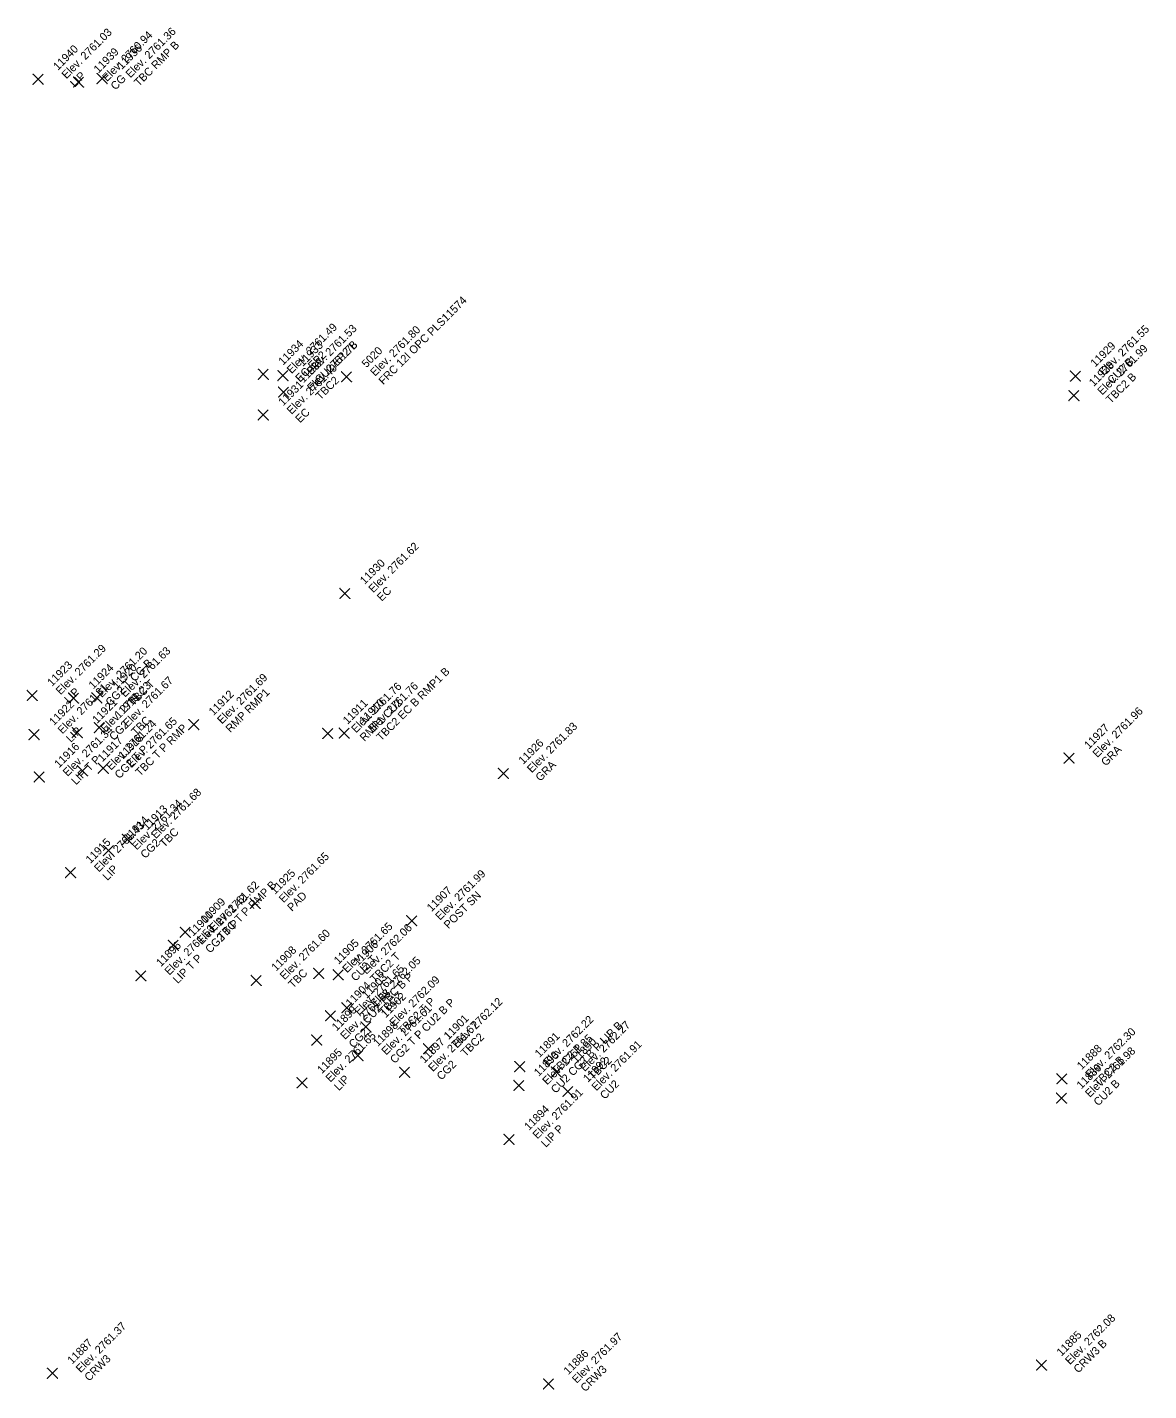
# Model space of a CAD drawing. Extents: x 2493999 to 2503109, y 700767 to 706646.
# Drawn here: x 2502309.37 to 2502343.02, y 701969.92 to 702010.81 of the extents above; entities that cross this region are included whole.
import ezdxf

# ---------------------------------------------------------------- set-up
doc = ezdxf.new("R2010")
doc.units = 0
doc.layers.add('ALG_CL_BLUE_Horiz', color=7, linetype='Continuous')
doc.layers.add('DES_SURFACE_Existing-Ground', color=7, linetype='Continuous')

msp = doc.modelspace()

# ---------------------------------------------------------------- linework, layer by layer
at = {"layer": 'ALG_CL_BLUE_Horiz'}
for points in [[(2502309.698, 702009.247), (2502309.548, 702009.397), (2502309.698, 702009.247), (2502309.548, 702009.097), (2502309.698, 702009.247), (2502309.848, 702009.097), (2502309.698, 702009.247), (2502309.848, 702009.397)], [(2502310.914, 702009.163), (2502310.764, 702009.313), (2502310.914, 702009.163), (2502310.764, 702009.013), (2502310.914, 702009.163), (2502311.064, 702009.013), (2502310.914, 702009.163), (2502311.064, 702009.313)], [(2502311.617, 702009.271), (2502311.467, 702009.421), (2502311.617, 702009.271), (2502311.467, 702009.121), (2502311.617, 702009.271), (2502311.767, 702009.121), (2502311.617, 702009.271), (2502311.767, 702009.421)], [(2502316.456, 702000.403), (2502316.306, 702000.553), (2502316.456, 702000.403), (2502316.306, 702000.253), (2502316.456, 702000.403), (2502316.606, 702000.253), (2502316.456, 702000.403), (2502316.606, 702000.553)], [(2502317.043, 702000.364), (2502316.893, 702000.514), (2502317.043, 702000.364), (2502316.893, 702000.214), (2502317.043, 702000.364), (2502317.193, 702000.214), (2502317.043, 702000.364), (2502317.193, 702000.514)], [(2502318.954, 702000.326), (2502318.804, 702000.476), (2502318.954, 702000.326), (2502318.804, 702000.176), (2502318.954, 702000.326), (2502319.104, 702000.176), (2502318.954, 702000.326), (2502319.104, 702000.476)], [(2502340.821, 702000.346), (2502340.671, 702000.496), (2502340.821, 702000.346), (2502340.671, 702000.196), (2502340.821, 702000.346), (2502340.971, 702000.196), (2502340.821, 702000.346), (2502340.971, 702000.496)], [(2502317.065, 701999.869), (2502316.915, 702000.019), (2502317.065, 701999.869), (2502316.915, 701999.719), (2502317.065, 701999.869), (2502317.215, 701999.719), (2502317.065, 701999.869), (2502317.215, 702000.019)], [(2502340.775, 701999.764), (2502340.625, 701999.914), (2502340.775, 701999.764), (2502340.625, 701999.614), (2502340.775, 701999.764), (2502340.925, 701999.614), (2502340.775, 701999.764), (2502340.925, 701999.914)], [(2502316.455, 701999.181), (2502316.305, 701999.331), (2502316.455, 701999.181), (2502316.305, 701999.031), (2502316.455, 701999.181), (2502316.605, 701999.031), (2502316.455, 701999.181), (2502316.605, 701999.331)], [(2502318.904, 701993.83), (2502318.754, 701993.98), (2502318.904, 701993.83), (2502318.754, 701993.68), (2502318.904, 701993.83), (2502319.054, 701993.68), (2502318.904, 701993.83), (2502319.054, 701993.98)], [(2502309.523, 701990.772), (2502309.373, 701990.922), (2502309.523, 701990.772), (2502309.373, 701990.622), (2502309.523, 701990.772), (2502309.673, 701990.622), (2502309.523, 701990.772), (2502309.673, 701990.922)], [(2502310.762, 701990.69), (2502310.612, 701990.84), (2502310.762, 701990.69), (2502310.612, 701990.54), (2502310.762, 701990.69), (2502310.912, 701990.54), (2502310.762, 701990.69), (2502310.912, 701990.84)], [(2502311.458, 701990.698), (2502311.308, 701990.848), (2502311.458, 701990.698), (2502311.308, 701990.548), (2502311.458, 701990.698), (2502311.608, 701990.548), (2502311.458, 701990.698), (2502311.608, 701990.848)], [(2502314.366, 701989.896), (2502314.216, 701990.046), (2502314.366, 701989.896), (2502314.216, 701989.746), (2502314.366, 701989.896), (2502314.516, 701989.746), (2502314.366, 701989.896), (2502314.516, 701990.046)], [(2502309.579, 701989.597), (2502309.429, 701989.747), (2502309.579, 701989.597), (2502309.429, 701989.447), (2502309.579, 701989.597), (2502309.729, 701989.447), (2502309.579, 701989.597), (2502309.729, 701989.747)], [(2502310.872, 701989.655), (2502310.722, 701989.805), (2502310.872, 701989.655), (2502310.722, 701989.505), (2502310.872, 701989.655), (2502311.022, 701989.505), (2502310.872, 701989.655), (2502311.022, 701989.805)], [(2502311.535, 701989.804), (2502311.385, 701989.954), (2502311.535, 701989.804), (2502311.385, 701989.654), (2502311.535, 701989.804), (2502311.685, 701989.654), (2502311.535, 701989.804), (2502311.685, 701989.954)], [(2502318.389, 701989.63), (2502318.239, 701989.78), (2502318.389, 701989.63), (2502318.239, 701989.48), (2502318.389, 701989.63), (2502318.539, 701989.48), (2502318.389, 701989.63), (2502318.539, 701989.78)], [(2502318.885, 701989.641), (2502318.735, 701989.791), (2502318.885, 701989.641), (2502318.735, 701989.491), (2502318.885, 701989.641), (2502319.035, 701989.491), (2502318.885, 701989.641), (2502319.035, 701989.791)], [(2502340.63, 701988.891), (2502340.48, 701989.041), (2502340.63, 701988.891), (2502340.48, 701988.741), (2502340.63, 701988.891), (2502340.78, 701988.741), (2502340.63, 701988.891), (2502340.78, 701989.041)], [(2502309.734, 701988.326), (2502309.584, 701988.476), (2502309.734, 701988.326), (2502309.584, 701988.176), (2502309.734, 701988.326), (2502309.884, 701988.176), (2502309.734, 701988.326), (2502309.884, 701988.476)], [(2502311.034, 701988.51), (2502310.884, 701988.66), (2502311.034, 701988.51), (2502310.884, 701988.36), (2502311.034, 701988.51), (2502311.184, 701988.36), (2502311.034, 701988.51), (2502311.184, 701988.66)], [(2502311.654, 701988.588), (2502311.504, 701988.738), (2502311.654, 701988.588), (2502311.504, 701988.438), (2502311.654, 701988.588), (2502311.804, 701988.438), (2502311.654, 701988.588), (2502311.804, 701988.738)], [(2502323.661, 701988.433), (2502323.511, 701988.583), (2502323.661, 701988.433), (2502323.511, 701988.283), (2502323.661, 701988.433), (2502323.811, 701988.283), (2502323.661, 701988.433), (2502323.811, 701988.583)], [(2502312.38, 701986.455), (2502312.23, 701986.605), (2502312.38, 701986.455), (2502312.23, 701986.305), (2502312.38, 701986.455), (2502312.53, 701986.305), (2502312.38, 701986.455), (2502312.53, 701986.605)], [(2502311.809, 701986.118), (2502311.659, 701986.268), (2502311.809, 701986.118), (2502311.659, 701985.968), (2502311.809, 701986.118), (2502311.959, 701985.968), (2502311.809, 701986.118), (2502311.959, 701986.268)], [(2502310.672, 701985.458), (2502310.522, 701985.608), (2502310.672, 701985.458), (2502310.522, 701985.308), (2502310.672, 701985.458), (2502310.822, 701985.308), (2502310.672, 701985.458), (2502310.822, 701985.608)], [(2502316.214, 701984.533), (2502316.064, 701984.683), (2502316.214, 701984.533), (2502316.064, 701984.383), (2502316.214, 701984.533), (2502316.364, 701984.383), (2502316.214, 701984.533), (2502316.364, 701984.683)], [(2502320.909, 701984.013), (2502320.759, 701984.163), (2502320.909, 701984.013), (2502320.759, 701983.863), (2502320.909, 701984.013), (2502321.059, 701983.863), (2502320.909, 701984.013), (2502321.059, 701984.163)], [(2502314.114, 701983.671), (2502313.964, 701983.821), (2502314.114, 701983.671), (2502313.964, 701983.521), (2502314.114, 701983.671), (2502314.264, 701983.521), (2502314.114, 701983.671), (2502314.264, 701983.821)], [(2502313.753, 701983.28), (2502313.603, 701983.43), (2502313.753, 701983.28), (2502313.603, 701983.13), (2502313.753, 701983.28), (2502313.903, 701983.13), (2502313.753, 701983.28), (2502313.903, 701983.43)], [(2502312.785, 701982.365), (2502312.635, 701982.515), (2502312.785, 701982.365), (2502312.635, 701982.215), (2502312.785, 701982.365), (2502312.935, 701982.215), (2502312.785, 701982.365), (2502312.935, 701982.515)], [(2502316.245, 701982.226), (2502316.095, 701982.376), (2502316.245, 701982.226), (2502316.095, 701982.076), (2502316.245, 701982.226), (2502316.395, 701982.076), (2502316.245, 701982.226), (2502316.395, 701982.376)], [(2502318.12, 701982.435), (2502317.97, 701982.585), (2502318.12, 701982.435), (2502317.97, 701982.285), (2502318.12, 701982.435), (2502318.27, 701982.285), (2502318.12, 701982.435), (2502318.27, 701982.585)], [(2502318.702, 701982.392), (2502318.552, 701982.542), (2502318.702, 701982.392), (2502318.552, 701982.242), (2502318.702, 701982.392), (2502318.852, 701982.242), (2502318.702, 701982.392), (2502318.852, 701982.542)], [(2502318.963, 701981.407), (2502318.813, 701981.557), (2502318.963, 701981.407), (2502318.813, 701981.257), (2502318.963, 701981.407), (2502319.113, 701981.257), (2502318.963, 701981.407), (2502319.113, 701981.557)], [(2502318.474, 701981.164), (2502318.324, 701981.314), (2502318.474, 701981.164), (2502318.324, 701981.014), (2502318.474, 701981.164), (2502318.624, 701981.014), (2502318.474, 701981.164), (2502318.624, 701981.314)], [(2502319.533, 701980.831), (2502319.383, 701980.981), (2502319.533, 701980.831), (2502319.383, 701980.681), (2502319.533, 701980.831), (2502319.683, 701980.681), (2502319.533, 701980.831), (2502319.683, 701980.981)], [(2502318.058, 701980.434), (2502317.908, 701980.584), (2502318.058, 701980.434), (2502317.908, 701980.284), (2502318.058, 701980.434), (2502318.208, 701980.284), (2502318.058, 701980.434), (2502318.208, 701980.584)], [(2502321.416, 701980.175), (2502321.266, 701980.325), (2502321.416, 701980.175), (2502321.266, 701980.025), (2502321.416, 701980.175), (2502321.566, 701980.025), (2502321.416, 701980.175), (2502321.566, 701980.325)], [(2502319.296, 701979.969), (2502319.146, 701980.119), (2502319.296, 701979.969), (2502319.146, 701979.819), (2502319.296, 701979.969), (2502319.446, 701979.819), (2502319.296, 701979.969), (2502319.446, 701980.119)], [(2502324.147, 701979.64), (2502323.997, 701979.79), (2502324.147, 701979.64), (2502323.997, 701979.49), (2502324.147, 701979.64), (2502324.297, 701979.49), (2502324.147, 701979.64), (2502324.297, 701979.79)], [(2502320.696, 701979.472), (2502320.546, 701979.622), (2502320.696, 701979.472), (2502320.546, 701979.322), (2502320.696, 701979.472), (2502320.846, 701979.322), (2502320.696, 701979.472), (2502320.846, 701979.622)], [(2502325.25, 701979.474), (2502325.1, 701979.624), (2502325.25, 701979.474), (2502325.1, 701979.324), (2502325.25, 701979.474), (2502325.4, 701979.324), (2502325.25, 701979.474), (2502325.4, 701979.624)], [(2502340.414, 701979.275), (2502340.264, 701979.425), (2502340.414, 701979.275), (2502340.264, 701979.125), (2502340.414, 701979.275), (2502340.564, 701979.125), (2502340.414, 701979.275), (2502340.564, 701979.425)], [(2502317.617, 701979.156), (2502317.467, 701979.306), (2502317.617, 701979.156), (2502317.467, 701979.006), (2502317.617, 701979.156), (2502317.767, 701979.006), (2502317.617, 701979.156), (2502317.767, 701979.306)], [(2502324.123, 701979.075), (2502323.973, 701979.225), (2502324.123, 701979.075), (2502323.973, 701978.925), (2502324.123, 701979.075), (2502324.273, 701978.925), (2502324.123, 701979.075), (2502324.273, 701979.225)], [(2502325.596, 701978.896), (2502325.446, 701979.046), (2502325.596, 701978.896), (2502325.446, 701978.746), (2502325.596, 701978.896), (2502325.746, 701978.746), (2502325.596, 701978.896), (2502325.746, 701979.046)], [(2502340.405, 701978.697), (2502340.255, 701978.847), (2502340.405, 701978.697), (2502340.255, 701978.547), (2502340.405, 701978.697), (2502340.555, 701978.547), (2502340.405, 701978.697), (2502340.555, 701978.847)], [(2502323.831, 701977.454), (2502323.681, 701977.604), (2502323.831, 701977.454), (2502323.681, 701977.304), (2502323.831, 701977.454), (2502323.981, 701977.304), (2502323.831, 701977.454), (2502323.981, 701977.604)], [(2502339.805, 701970.687), (2502339.655, 701970.837), (2502339.805, 701970.687), (2502339.655, 701970.537), (2502339.805, 701970.687), (2502339.955, 701970.537), (2502339.805, 701970.687), (2502339.955, 701970.837)], [(2502310.127, 701970.443), (2502309.977, 701970.593), (2502310.127, 701970.443), (2502309.977, 701970.293), (2502310.127, 701970.443), (2502310.277, 701970.293), (2502310.127, 701970.443), (2502310.277, 701970.593)], [(2502325.012, 701970.126), (2502324.862, 701970.276), (2502325.012, 701970.126), (2502324.862, 701969.976), (2502325.012, 701970.126), (2502325.162, 701969.976), (2502325.012, 701970.126), (2502325.162, 701970.276)]]:
    msp.add_lwpolyline(points, dxfattribs=at)

# ---------------------------------------------------------------- texts
at = {"layer": 'DES_SURFACE_Existing-Ground'}
for s, p in [('Elev. 2761.03', (2502310.547, 702009.247)), ('Elev. 2760.94', (2502311.763, 702009.163)), ('Elev. 2761.36', (2502312.466, 702009.271)), ('11940', (2502310.292, 702009.502)), ('11939', (2502311.508, 702009.418)), ('11936', (2502312.211, 702009.526)), ('TBC RMP B', (2502312.72, 702009.016)), ('LIP', (2502310.801, 702008.992)), ('CG', (2502312.017, 702008.908)), ('FRC 12I OPC PLS11574', (2502320.057, 702000.071)), ('Elev. 2761.49', (2502317.305, 702000.403)), ('Elev. 2761.53', (2502317.892, 702000.364)), ('Elev. 2761.55', (2502341.67, 702000.346)), ('Elev. 2761.80', (2502319.803, 702000.326)), ('11934', (2502317.05, 702000.658)), ('EC EP2', (2502317.559, 702000.148)), ('11933', (2502317.637, 702000.619)), ('Elev. 2761.78', (2502317.914, 701999.869)), ('CU2 EP2 B', (2502318.146, 702000.109)), ('5020', (2502319.548, 702000.581)), ('11929', (2502341.415, 702000.601)), ('Elev. 2761.99', (2502341.624, 701999.764)), ('Elev. 2761.49', (2502317.304, 701999.181)), ('11932', (2502317.659, 702000.124)), ('11928', (2502341.369, 702000.019)), ('CU2 B', (2502341.924, 702000.091)), ('TBC2', (2502318.168, 701999.614)), ('TBC2 B', (2502341.878, 701999.509)), ('11931', (2502317.049, 701999.436)), ('EC', (2502317.558, 701998.926)), ('Elev. 2761.62', (2502319.753, 701993.83)), ('11930', (2502319.498, 701994.085)), ('EC', (2502320.007, 701993.575)), ('Elev. 2761.29', (2502310.372, 701990.772)), ('Elev. 2761.20', (2502311.611, 701990.69)), ('Elev. 2761.63', (2502312.307, 701990.698)), ('11923', (2502310.117, 701991.027)), ('11924', (2502311.356, 701990.945)), ('CG2 T CG B', (2502311.865, 701990.435)), ('11920', (2502312.052, 701990.953)), ('Elev. 2761.67', (2502312.384, 701989.804)), ('TBC T', (2502312.561, 701990.443)), ('Elev. 2761.69', (2502315.215, 701989.896)), ('TBC2 EC B RMP1 B', (2502319.988, 701989.386)), ('Elev. 2761.31', (2502310.428, 701989.597)), ('LIP', (2502310.626, 701990.517)), ('Elev. 2761.23', (2502311.721, 701989.655)), ('11919', (2502312.129, 701990.059)), ('11912', (2502314.96, 701990.151)), ('RMP RMP1', (2502315.469, 701989.641)), ('Elev. 2761.76', (2502319.238, 701989.63)), ('Elev. 2761.76', (2502319.734, 701989.641)), ('11922', (2502310.173, 701989.852)), ('11921', (2502311.466, 701989.91)), ('11911', (2502318.983, 701989.885)), ('RMP1 CU2', (2502319.492, 701989.375)), ('11910', (2502319.479, 701989.896)), ('Elev. 2761.96', (2502341.479, 701988.891)), ('Elev. 2761.24', (2502311.883, 701988.51)), ('CG2', (2502311.975, 701989.4)), ('Elev. 2761.65', (2502312.503, 701988.588)), ('TBC', (2502312.638, 701989.549)), ('Elev. 2761.34', (2502310.583, 701988.326)), ('LIP', (2502310.682, 701989.342)), ('11918', (2502312.248, 701988.843)), ('TBC T P RMP', (2502312.757, 701988.333)), ('Elev. 2761.83', (2502324.51, 701988.433)), ('11927', (2502341.224, 701989.146)), ('11916', (2502310.328, 701988.581)), ('11917', (2502311.628, 701988.765)), ('CG2 T P', (2502312.137, 701988.255)), ('11926', (2502324.255, 701988.688)), ('GRA', (2502341.733, 701988.636)), ('LIP T P', (2502310.837, 701988.071)), ('GRA', (2502324.764, 701988.178)), ('Elev. 2761.68', (2502313.229, 701986.455)), ('Elev. 2761.34', (2502312.658, 701986.118)), ('11914', (2502312.403, 701986.373)), ('11913', (2502312.974, 701986.71)), ('Elev. 2761.43', (2502311.521, 701985.458)), ('TBC', (2502313.483, 701986.2)), ('11915', (2502311.266, 701985.713)), ('CG2', (2502312.912, 701985.863)), ('Elev. 2761.65', (2502317.063, 701984.533)), ('LIP', (2502311.775, 701985.203)), ('11925', (2502316.808, 701984.788)), ('Elev. 2761.99', (2502321.758, 701984.013)), ('Elev. 2761.62', (2502314.963, 701983.671)), ('TBC T P RMP B', (2502315.217, 701983.416)), ('Elev. 2761.42', (2502314.602, 701983.28)), ('11909', (2502314.708, 701983.926)), ('PAD', (2502317.317, 701984.278)), ('11907', (2502321.503, 701984.268)), ('POST SN', (2502322.012, 701983.758)), ('11900', (2502314.347, 701983.535)), ('Elev. 2761.53', (2502313.634, 701982.365)), ('CG2 T P', (2502314.856, 701983.025)), ('Elev. 2761.65', (2502318.969, 701982.435)), ('Elev. 2762.06', (2502319.551, 701982.392)), ('Elev. 2761.60', (2502317.094, 701982.226)), ('11905', (2502318.714, 701982.69)), ('11896', (2502313.379, 701982.62)), ('11908', (2502316.839, 701982.481)), ('11906', (2502319.296, 701982.647)), ('TBC2 T', (2502319.805, 701982.137)), ('LIP T P', (2502313.888, 701982.11)), ('CU2 T', (2502319.223, 701982.18)), ('Elev. 2761.65', (2502319.323, 701981.164)), ('Elev. 2762.05', (2502319.812, 701981.407)), ('TBC', (2502317.348, 701981.971)), ('11903', (2502319.557, 701981.662)), ('CU2 TBC B P', (2502319.577, 701980.909)), ('Elev. 2762.09', (2502320.382, 701980.831)), ('Elev. 2761.58', (2502318.907, 701980.434)), ('11904', (2502319.068, 701981.419)), ('TBC2', (2502320.066, 701981.152)), ('11902', (2502320.127, 701981.086)), ('11899', (2502318.652, 701980.689)), ('Elev. 2761.61', (2502320.145, 701979.969)), ('CG2 T P CU2 B P', (2502320.399, 701979.714)), ('TBC2 T P', (2502320.636, 701980.576)), ('Elev. 2762.12', (2502322.265, 701980.175)), ('Elev. 2761.67', (2502321.545, 701979.472)), ('11901', (2502322.01, 701980.43)), ('Elev. 2762.22', (2502324.996, 701979.64)), ('Elev. 2762.27', (2502326.099, 701979.474)), ('Elev. 2761.65', (2502318.466, 701979.156)), ('CG2', (2502319.161, 701980.179)), ('11898', (2502319.89, 701980.224)), ('TBC2', (2502322.519, 701979.92)), ('11891', (2502324.741, 701979.895)), ('Elev. 2761.85', (2502324.972, 701979.075)), ('CU2 CG2 B P LIP B', (2502325.226, 701978.82)), ('Elev. 2762.30', (2502341.263, 701979.275)), ('11895', (2502318.211, 701979.411)), ('11897', (2502321.29, 701979.727)), ('TBC2 P', (2502325.25, 701979.385)), ('11890', (2502325.844, 701979.729)), ('Elev. 2761.91', (2502326.445, 701978.896)), ('11888', (2502341.008, 701979.53)), ('Elev. 2761.98', (2502341.254, 701978.697)), ('CG2', (2502321.799, 701979.217)), ('11893', (2502324.717, 701979.33)), ('11892', (2502326.19, 701979.151)), ('TBC2', (2502326.353, 701979.219)), ('TBC2 B', (2502341.517, 701979.02)), ('LIP', (2502318.72, 701978.901)), ('11889', (2502340.999, 701978.952)), ('Elev. 2761.91', (2502324.68, 701977.454)), ('CU2', (2502326.699, 701978.641)), ('CU2 B', (2502341.508, 701978.442)), ('11894', (2502324.425, 701977.709)), ('LIP P', (2502324.934, 701977.199)), ('Elev. 2762.08', (2502340.654, 701970.687)), ('Elev. 2761.37', (2502310.976, 701970.443)), ('Elev. 2761.97', (2502325.861, 701970.126)), ('11885', (2502340.399, 701970.942)), ('11887', (2502310.721, 701970.698)), ('CRW3 B', (2502340.908, 701970.432)), ('CRW3', (2502311.23, 701970.188)), ('11886', (2502325.606, 701970.381)), ('CRW3', (2502326.115, 701969.871))]:
    msp.add_text(s, height=0.24, rotation=45, dxfattribs=at).set_placement(p)

doc.saveas('drawing.dxf')
